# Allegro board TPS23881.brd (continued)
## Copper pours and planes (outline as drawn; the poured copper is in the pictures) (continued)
PSE_D8 on TOP: 27.38,67.26 29.67,67.26 29.79,67.13 29.79,59.64 29.67,59.51 25.1,59.51 24.97,59.64 24.97,64.34 25.22,64.59 27,64.59 27.25,64.85 27.25,67.13
PSE_SEN1 on TOP: 2.74,47.45 5.79,47.45 5.92,47.32 5.92,45.54 5.79,45.42 2.87,45.42 2.62,45.67 2.62,47.32
PSE_SEN1 on BOTTOM: 2.74,47.96 4.9,47.96 5.03,47.83 5.03,45.54 4.9,45.42 2.74,45.42 2.62,45.54 2.62,47.83
PSE_SEN2 on TOP: 10.24,47.45 13.28,47.45 13.41,47.32 13.41,45.54 13.28,45.42 10.36,45.42 10.11,45.67 10.11,47.32
PSE_SEN2 on BOTTOM: 10.24,47.96 12.4,47.96 12.52,47.83 12.52,45.54 12.4,45.42 10.24,45.42 10.11,45.54 10.11,47.83
PSE_SEN3 on TOP: 2.74,58.75 5.79,58.75 5.92,58.62 5.92,56.85 5.79,56.72 2.87,56.72 2.62,56.97 2.62,58.62
PSE_SEN3 on BOTTOM: 2.74,59.26 4.9,59.26 5.03,59.13 5.03,56.85 4.9,56.72 2.74,56.72 2.62,56.85 2.62,59.13
PSE_SEN4 on TOP: 10.24,58.75 13.28,58.75 13.41,58.62 13.41,56.85 13.28,56.72 10.36,56.72 10.11,56.97 10.11,58.62
PSE_SEN4 on BOTTOM: 10.24,59.26 12.4,59.26 12.52,59.13 12.52,56.85 12.4,56.72 10.24,56.72 10.11,56.85 10.11,59.13
PSE_SEN5 on TOP: 17.73,47.45 20.78,47.45 20.9,47.32 20.9,45.54 20.78,45.42 17.86,45.42 17.6,45.67 17.6,47.32
PSE_SEN5 on BOTTOM: 17.73,47.96 19.89,47.96 20.02,47.83 20.02,45.54 19.89,45.42 17.73,45.42 17.6,45.54 17.6,47.83
PSE_SEN6 on TOP: 17.73,58.75 20.78,58.75 20.9,58.62 20.9,56.85 20.78,56.72 17.86,56.72 17.6,56.97 17.6,58.62
PSE_SEN6 on BOTTOM: 17.73,59.26 19.89,59.26 20.02,59.13 20.02,56.85 19.89,56.72 17.73,56.72 17.6,56.85 17.6,59.13
PSE_SEN7 on TOP: 25.22,47.45 28.27,47.45 28.4,47.32 28.4,45.54 28.27,45.42 25.35,45.42 25.1,45.67 25.1,47.32
PSE_SEN7 on BOTTOM: 25.22,47.96 27.38,47.96 27.51,47.83 27.51,45.54 27.38,45.42 25.22,45.42 25.1,45.54 25.1,47.83
PSE_SEN8 on TOP: 25.22,58.75 28.27,58.75 28.4,58.62 28.4,56.85 28.27,56.72 25.35,56.72 25.1,56.97 25.1,58.62
PSE_SEN8 on BOTTOM: 25.22,59.26 27.38,59.26 27.51,59.13 27.51,56.85 27.38,56.72 25.22,56.72 25.1,56.85 25.1,59.13
RX_PAVDD_A on BOTTOM: 95.66,91.19 99.97,91.19 100.23,90.93 101.37,90.93 101.5,90.81 101.5,89.92 101.37,89.79 99.59,89.79 99.34,89.53 94.77,89.53 94.64,89.66 94.64,90.81 94.77,90.93 95.4,90.93
TX_AVDD_A on BOTTOM: 94.01,82.04 96.55,82.04 97.05,82.55 98.32,82.55 99.21,83.44 100.23,83.44 100.48,83.69 101.24,83.69 101.37,83.57 101.37,81.28 101.24,81.15 97.82,81.15 97.69,81.03 97.05,81.03 96.93,80.9 96.55,80.9 96.42,81.03 94.89,81.03 94.77,80.9 94.01,80.9 93.88,81.03 93.88,81.92
USB_GND on TOP: 77.47,198.5 78.87,198.5 78.99,198.37 78.99,197.1 79.76,196.34 80.9,196.34 84.71,192.53 84.71,183.39 84.58,183.26 82.3,183.26 82.17,183.39 82.17,185.42 82.55,185.8 82.55,190.5 82.3,190.75 80.39,190.75 77.34,193.8 77.34,198.37
USB_GND on BOTTOM: 82.68,185.42 84.07,185.42 84.2,185.29 84.2,183.13 84.07,183.01 82.68,183.01 82.55,183.13 82.55,185.29
VP10_HUB on TOP: 82.58,60.12 82.58,59.41 82.52,59.36 81.86,59.36 81.79,59.44 81.79,60.38 81.74,60.43 81.74,60.63 81.81,60.71 81.81,61.26 81.92,61.37 82.55,61.37 82.6,61.32 82.6,60.86 82.75,60.71 82.75,60.3
VP10_HUB on BOTTOM: 78.64,72.72 84.02,72.72 84.79,71.96 88.98,71.96 89.36,71.58 89.36,62.18 87.83,60.66 86.56,60.66 86.06,60.15 81.48,60.15 80.34,61.29 77.04,61.29 76.02,62.31 76.02,66.34 76.61,66.93 77.24,66.93 78.38,68.07 78.38,72.47
N16705548 on TOP: 41.53,161.8 47.62,161.8 47.88,161.54 47.88,152.98 46.41,151.51 38.1,151.51 37.85,151.76 37.85,157.1 37.97,157.23 40.89,157.23 41.4,157.73 41.4,161.67
N16715221 on BOTTOM (solid shape): 18.31,126.34 18.31,120.29 18.03,120.02 12.09,120.02 11.84,120.27 11.84,120.78 12.22,121.16 12.22,124.33 12.47,124.59 12.99,124.59 13.12,124.71 13.12,126.48 13.26,126.62 18.03,126.62
N16715221 on TOP: 18.16,120.14 18.03,120.02 11.05,120.02 10.79,120.27 10.79,124.33 10.92,124.46 12.32,124.46 12.7,124.84 12.7,126.06 13.26,126.62 18.03,126.62 18.16,126.49
N16715269 on BOTTOM (solid shape): 18.31,135.13 18.31,127.51 18.06,127.25 13.87,127.25 12.14,128.98 12.14,135.13 12.4,135.38 18.06,135.38
N16715269 on TOP: 18.54,127.76 18.03,127.25 13.87,127.25 12.14,128.98 12.14,135.13 12.4,135.38 18.41,135.38 18.54,135.25
N16715396 on TOP: 34.54,119.51 34.37,119.33 27.89,119.33 27.43,119.79 27.43,124.33 27.56,124.46 29.34,124.46 29.46,124.59 29.46,127.76 29.21,128.02 22.48,128.02 22.35,128.14 22.35,135.38 22.68,135.71 34.11,135.71 34.54,135.28
N16715396 on BOTTOM: 34.62,119.58 34.37,119.33 30.12,119.33 29.78,119.67 29.78,128.36 29.41,128.73 27.64,128.73 27.46,128.91 27.46,130.56 27.08,130.94 23.39,130.94 23.14,131.19 23.14,135.33 23.52,135.71 34.24,135.71 34.62,135.33
N16716334 on TOP: 26.54,119.51 26.37,119.33 21.92,119.33 21.72,119.53 21.72,127.25 21.84,127.38 26.29,127.38 26.54,127.13
N16716334 on BOTTOM: 22.63,130.38 26.49,130.38 26.82,130.05 26.82,125.86 29.03,123.65 29.03,117.3 28.91,117.17 22.94,117.17 22.68,117.42 22.68,124.16 22.25,124.59 22.25,130
N16718141 on BOTTOM (solid shape): 21.41,133.05 21.41,131.27 21.29,131.14 18.87,131.14 18.75,131.27 18.75,133.05 18.87,133.17 21.29,133.17
N17477531 on TOP: 40.18,11.48 41.55,11.48 41.66,11.38 41.66,9.5 41.58,9.42 40.18,9.42 40.06,9.55 40.06,11.35
N17477531 on BOTTOM: 40.87,10.31 40.72,10.16 40.72,7.9 40.69,7.87 40.08,7.87 40.06,7.9 40.06,11.35 40.18,11.48 41.55,11.48 41.66,11.38 41.66,10.39 41.58,10.31
N17477559 on TOP: 44.45,11.51 45.54,11.51 45.62,11.43 45.62,9.42 45.54,9.35 44.48,9.35 44.37,9.45 44.37,11.43
N17477559 on BOTTOM: 45.64,11.43 45.64,10.34 45.57,10.26 43.81,10.26 43.71,10.16 43.71,7.9 43.69,7.87 43.08,7.87 43.05,7.9 43.05,11.38 43.18,11.51 45.57,11.51
N17486352 on TOP: 60.38,11.48 61.75,11.48 61.85,11.38 61.85,9.5 61.77,9.42 60.38,9.42 60.25,9.55 60.25,11.35
N17486352 on BOTTOM: 61.14,10.39 60.91,10.16 60.91,7.9 60.88,7.87 60.27,7.87 60.25,7.9 60.25,11.35 60.38,11.48 61.75,11.48 61.85,11.38 61.85,10.44 61.8,10.39
N17486475 on TOP: 64.64,11.51 65.74,11.51 65.81,11.43 65.81,9.42 65.74,9.35 64.67,9.35 64.57,9.45 64.57,11.43
N17486475 on BOTTOM: 65.84,11.43 65.84,10.34 65.76,10.26 64.01,10.26 63.91,10.16 63.91,7.9 63.88,7.87 63.27,7.87 63.25,7.9 63.25,11.38 63.37,11.51 65.76,11.51
N17487128 on TOP: 80.57,11.48 81.94,11.48 82.04,11.38 82.04,9.5 81.97,9.42 80.57,9.42 80.44,9.55 80.44,11.35
N17487128 on BOTTOM: 81.1,10.08 81.1,7.9 81.08,7.87 80.47,7.87 80.44,7.9 80.44,11.35 80.57,11.48 81.94,11.48 82.04,11.38 82.04,10.31 81.94,10.21 81.23,10.21
N17487156 on TOP: 84.84,11.51 85.93,11.51 86,11.43 86,9.42 85.93,9.35 84.86,9.35 84.76,9.45 84.76,11.43
N17487156 on BOTTOM: 86.03,11.43 86.03,10.34 85.95,10.26 84.2,10.26 84.1,10.16 84.1,7.9 84.07,7.87 83.46,7.87 83.44,7.9 83.44,11.38 83.57,11.51 85.95,11.51
N17488314 on TOP: 100.76,11.48 102.13,11.48 102.23,11.38 102.23,9.5 102.16,9.42 100.76,9.42 100.63,9.55 100.63,11.35
N17488314 on BOTTOM: 101.45,10.31 101.3,10.16 101.3,7.9 101.27,7.87 100.66,7.87 100.63,7.9 100.63,11.35 100.76,11.48 102.13,11.48 102.23,11.38 102.23,10.39 102.16,10.31
N17488336 on TOP: 105.03,11.51 106.12,11.51 106.2,11.43 106.2,9.42 106.12,9.35 105.05,9.35 104.95,9.45 104.95,11.43
N17488336 on BOTTOM: 106.22,11.43 106.22,10.34 106.15,10.26 104.39,10.26 104.29,10.16 104.29,7.9 104.27,7.87 103.66,7.87 103.63,7.9 103.63,11.38 103.76,11.51 106.15,11.51
N17488976 on TOP: 120.95,11.48 122.33,11.48 122.43,11.38 122.43,9.5 122.35,9.42 120.95,9.42 120.83,9.55 120.83,11.35
N17488976 on BOTTOM: 121.62,10.29 121.49,10.16 121.49,7.9 121.46,7.87 120.85,7.87 120.83,7.9 120.83,11.35 120.95,11.48 122.33,11.48 122.43,11.38 122.43,10.36 122.35,10.29
N17489028 on TOP: 125.22,11.51 126.31,11.51 126.39,11.43 126.39,9.42 126.31,9.35 125.25,9.35 125.15,9.45 125.15,11.43
N17489028 on BOTTOM: 126.42,11.43 126.42,10.34 126.34,10.26 124.59,10.26 124.49,10.16 124.49,7.9 124.46,7.87 123.85,7.87 123.83,7.9 123.83,11.38 123.95,11.51 126.34,11.51
N17489888 on TOP: 145.41,11.51 146.51,11.51 146.58,11.43 146.58,9.42 146.51,9.35 145.44,9.35 145.34,9.45 145.34,11.43
N17489888 on BOTTOM: 146.61,11.43 146.61,10.34 146.53,10.26 144.78,10.26 144.68,10.16 144.68,7.9 144.65,7.87 144.04,7.87 144.02,7.9 144.02,11.38 144.15,11.51 146.53,11.51
N17489893 on TOP: 141.15,11.48 142.52,11.48 142.62,11.38 142.62,9.5 142.54,9.42 141.15,9.42 141.02,9.55 141.02,11.35
N17489893 on BOTTOM: 141.68,9.91 141.68,7.9 141.66,7.87 141.05,7.87 141.02,7.9 141.02,11.35 141.15,11.48 142.14,11.48 142.15,11.47 142.58,11.47 142.62,11.43 142.62,10.29 142.49,10.16 141.94,10.16
N17490600 on TOP: 145.16,58.55 149.61,58.55 149.73,58.42 149.73,57.28 149.61,57.15 145.16,57.15 145.03,57.28 145.03,58.42
N17490600 on BOTTOM: 148.74,54.23 149.1,53.87 151.1,53.87 151.13,53.85 151.13,53.24 151.1,53.21 148.21,53.21 147.19,54.23 147.19,58.42 147.32,58.55 148.59,58.55 148.74,58.39
N17490605 on TOP: 145.16,52.32 145.16,53.59 145.29,53.72 149.73,53.72 149.86,53.59 149.86,52.7 149.61,52.45 147.83,52.45 147.57,52.2 145.29,52.2
N17490605 on BOTTOM: 151.1,50.88 151.13,50.85 151.13,50.24 151.1,50.22 147.14,50.22 146.43,50.93 146.43,53.09 146.69,53.34 147.45,53.34 148.46,52.32 148.46,51.31 148.89,50.88
N17490610 on TOP: 149.73,46.84 149.61,46.71 145.41,46.71 145.29,46.84 145.29,48.26 145.41,48.39 147.32,48.39 147.7,48.01 149.61,48.01 149.73,47.88
N17490610 on BOTTOM: 151.1,47.9 151.13,47.88 151.13,47.22 151.1,47.19 148.51,47.19 148.03,46.71 146.84,46.71 146.71,46.84 146.71,48.26 146.84,48.39 147.88,48.39 148.36,47.9
N17490615 on TOP: 149.73,43.94 149.73,42.16 149.61,42.04 145.41,42.04 145.29,42.16 145.29,43.81 145.54,44.07 149.61,44.07
N17490615 on BOTTOM: 147.98,44.88 151.23,44.88 151.41,44.7 151.41,42.8 151.28,42.67 147.35,42.67 147.22,42.8 147.22,44.12
N17524230 on TOP: 105.49,51.1 105.49,50.75 105.36,50.62 103.73,50.62 103.61,50.75 103.61,52.6 103.91,52.91 106.73,52.91 107.82,51.82 108.51,51.82 108.64,51.69 108.64,50.39 108.53,50.29 107.37,50.29 107.01,50.65 107.01,51.1 106.53,51.59 105.97,51.59
N18797950 on TOP: 22.86,182.25 22.99,182.12 22.99,179.32 24.38,177.93 24.38,174.24 24.26,174.12 14.61,174.12 14.48,174.24 14.48,181.86 14.86,182.25
N18797950 on BOTTOM: 14.61,181.36 18.03,181.36 18.16,181.23 18.16,179.45 18.54,179.07 22,179.07 23.95,177.11 26.37,177.11 26.49,176.99 26.49,172.54 26.37,172.42 22.56,172.42 20.85,174.12 14.61,174.12 14.48,174.24 14.48,181.23
N18798086 on BOTTOM (solid shape): 22.48,186.94 22.48,184.28 22.35,184.15 17.14,184.15 17.02,184.28 17.02,186.94 17.14,187.07 22.35,187.07
N18798086 on TOP: 22.35,187.07 22.48,186.94 22.48,184.28 22.35,184.15 17.14,184.15 17.02,184.28 17.02,186.94 17.14,187.07
N18799364 on TOP: 1.4,182.5 6.99,182.5 7.11,182.37 7.11,179.58 4.19,176.66 1.4,176.66 1.27,176.78 1.27,182.37
N18799364 on BOTTOM: 1.52,181.99 4.57,181.99 4.7,181.86 4.7,176.78 4.57,176.66 1.4,176.66 1.27,176.78 1.27,181.74
N198715748 on BOTTOM: 138.96,100.33 140.49,100.33 140.61,100.2 140.61,99.19 142.14,97.66 142.14,96.93 142.62,96.44 144.42,96.44 144.45,96.42 144.45,96.14 144.4,96.09 143.64,96.09 142.85,95.3 142.85,93.98 142.65,93.78 138.96,93.78 138.84,93.9 138.84,100.2
N236903803 on TOP: 139.6,88.01 144.68,88.01 144.81,87.88 144.81,84.71 144.68,84.58 138.07,84.58 137.82,84.84 135.66,84.84 135.53,84.96 135.53,85.34 135.66,85.47 137.31,85.47 139.34,87.5 139.34,87.76
N236903803 on BOTTOM: 132.99,85.98 137.82,85.98 139.34,87.5 139.34,87.76 139.6,88.01 144.68,88.01 144.81,87.88 144.81,83.69 144.68,83.57 142.01,83.57 141,84.58 138.07,84.58 137.82,84.84 135.79,84.84 135.15,85.47 132.99,85.47 132.87,85.6 132.87,85.85
N236903807 on BOTTOM: 127.79,87.25 131.09,87.25 131.34,87 131.34,86.11 131.47,85.98 132.49,85.98 132.61,85.85 132.61,85.34 132.74,85.22 135.03,85.22 135.15,85.09 135.15,84.84 135.03,84.71 133.38,84.71 132.99,84.33 132.99,83.06 132.74,82.8 127.79,82.8 127.66,82.93 127.66,87.12

Small or netless copper shapes (teardrops, artwork), in the pictures only: 8 on TOP, 8 on BOTTOM, 7 on IN1, 8 on IN2, 8 on IN3

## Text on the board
GND2: GND2
User.29: IN4
User.31: FIGURE | FINISHED_SIZE | 8.0 | 10.0 | 12.0 | 28.0 | 32.0 | 35.0 | 40.0 | 51.0 | 55.0 | 91.0 | 158.0 | 166.0 | 177.0 | 43.0 | 63.0 | 118.0 | 91.0x31.0 | DRILL CHART: TOP to BOTTOM | ALL UNITS ARE IN MILS | ROTATION | - | 90.000 | PLATED | NON-PLATED | QTY | 597 | 3892 | 771 | 50 | 126 | 12 | 28 | 7 | 6 | 2 | 3 | 9 | 4 | 14 | 5539 | TOTAL HOLES:
User.34: NOTES: | - MNC_LAYER: MUST-NOT-CUT-LAYER | - MAX_DEPTH: DEPTH FROM START LAYER TO THE | SURFACE OF MUST-NOT-CUT-LAYER | - MFG_STUB : MANUFACTURING STUB LENGTH | FIGURE | BD_SIZE | 8.0 | 10.0 | MNC_LAYER | IN3 | BACKDRILL: BOTTOM to GND2 | ALL UNITS ARE IN MILS | MAX_DEPTH | 9.35 | MFG_STUB | - | QTY | 4 | TOTAL BACKDRILLS: 8
